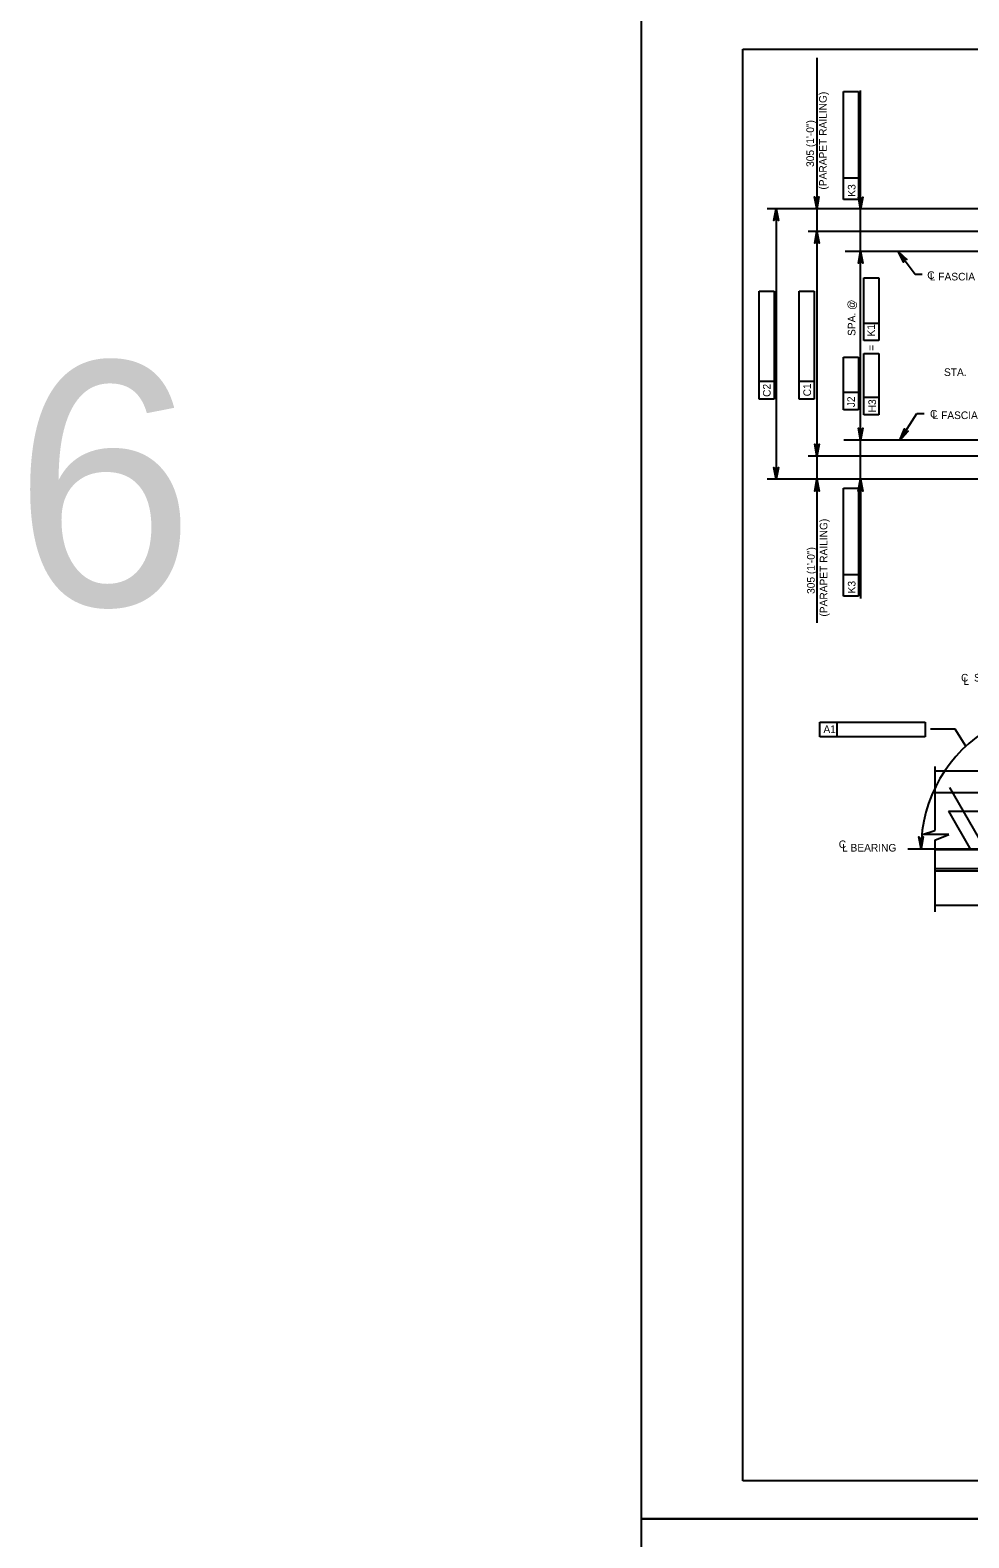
# Model space of a CAD drawing. Extents: x 638175 to 640495, y 294277 to 298435.
# Drawn here: x 638195 to 638564, y 294864 to 295458 of the extents above; entities that cross this region are included whole.
import ezdxf

# ---------------------------------------------------------------- set-up
doc = ezdxf.new("R2010")
doc.units = 0
for name, color, linetype in [('2', 7, 'Continuous'), ('3', 7, 'Continuous'), ('4', 7, 'Continuous'), ('5', 7, 'Continuous'), ('53', 7, 'Continuous'), ('8', 7, 'Continuous'), ('PLT-BNDY', 7, 'Continuous')]:
    doc.layers.add(name, color=color, linetype=linetype)

# ---------------------------------------------------------------- blocks, each defined once
blk = doc.blocks.new('AR')
at = {"layer": '4'}
blk.add_lwpolyline([(5, 0.833375), (5, -0.833375), (0, 0)], close=True, dxfattribs=at)

msp = doc.modelspace()

# ---------------------------------------------------------------- linework, layer by layer
at = {"layer": '2'}
for p, q in [((638475.46, 294886.46), (638475.46, 295450.46)), ((638475.46, 295450.46), (639261.46, 295450.46)), ((639261.46, 294886.46), (638475.46, 294886.46))]:
    msp.add_line(p, q, dxfattribs=at)
at = {"layer": '3'}
for p, q in [((638551.02, 295167.79), (638551.02, 295142.64)), ((638551.02, 295166.18), (638651.75, 295166.18)), ((638556.84, 295159.53), (638584.62, 295111.3)), ((638551.02, 295157.57), (638651.75, 295157.57)), ((638556.45, 295150.19), (638565.29, 295134.83)), ((638556.45, 295150.19), (638580.44, 295150.19)), ((638546.26, 295141.01), (638551.02, 295142.64)), ((638556.53, 295141.01), (638546.26, 295141.01)), ((638551.02, 295138.77), (638556.53, 295141.01)), ((638551.02, 295138.77), (638551.02, 295110.55)), ((638551.02, 295113.27), (638601.7, 295113.27))]:
    msp.add_line(p, q, dxfattribs=at)
at = {"layer": '4'}
for p, q in [((638504.6, 295447.04), (638504.6, 295224.4)), ((638515.12, 295391.26), (638515.12, 295433.78)), ((638515.12, 295433.78), (638521.03, 295433.78)), ((638521.03, 295433.78), (638521.03, 295391.26)), ((638521.8, 295362.21), (638521.8, 295434.13)), ((638521.03, 295399.64), (638515.12, 295399.64)), ((638521.03, 295391.26), (638515.12, 295391.26)), ((638521.8, 295390.3), (638521.8, 295393.14)), ((638657.4, 295387.6), (638485.03, 295387.6)), ((638488.54, 295387.6), (638488.54, 295281.03)), ((638667.7, 295378.63), (638501.09, 295378.63)), ((638863.78, 295370.8), (638515.73, 295370.8)), ((638536.58, 295370.8), (638543.26, 295361.87)), ((638521.8, 295280.88), (638521.8, 295362.21)), ((638543.26, 295361.87), (638546.09, 295361.87)), ((638481.87, 295355.15), (638487.77, 295355.15)), ((638481.87, 295312.63), (638481.87, 295355.15)), ((638487.77, 295355.15), (638487.77, 295312.63)), ((638497.59, 295312.61), (638497.59, 295355.13)), ((638497.59, 295355.13), (638503.5, 295355.13)), ((638503.5, 295355.13), (638503.5, 295312.61)), ((638523.09, 295360.37), (638529, 295360.37)), ((638523.09, 295335.72), (638523.09, 295360.37)), ((638529, 295360.37), (638529, 295335.72)), ((638529, 295342.42), (638523.09, 295342.42)), ((638529, 295335.72), (638523.09, 295335.72)), ((638515.1, 295329.07), (638521, 295329.07)), ((638515.1, 295308.35), (638515.1, 295329.07)), ((638521, 295329.07), (638521, 295308.35)), ((638523.09, 295306.34), (638523.09, 295330.59)), ((638523.09, 295330.59), (638529, 295330.59)), ((638529, 295330.59), (638529, 295306.34)), ((638487.77, 295319.52), (638481.87, 295319.52)), ((638503.5, 295319.5), (638497.59, 295319.5)), ((638521, 295315.24), (638515.1, 295315.24)), ((638529, 295313.23), (638523.09, 295313.23)), ((638487.77, 295312.63), (638481.87, 295312.63)), ((638503.5, 295312.61), (638497.59, 295312.61)), ((638521, 295308.35), (638515.1, 295308.35)), ((638529, 295306.34), (638523.09, 295306.34)), ((638537.32, 295296.45), (638544.03, 295306.88)), ((638544.03, 295306.88), (638546.86, 295306.88)), ((638825.02, 295296.45), (638515.26, 295296.45)), ((638609.48, 295290.15), (638501.09, 295290.15)), ((638598.75, 295281.03), (638485.03, 295281.03)), ((638515.12, 295234.98), (638515.12, 295277.5)), ((638515.12, 295277.5), (638521.03, 295277.5)), ((638521.03, 295277.5), (638521.03, 295234.98)), ((638521.8, 295278.31), (638521.8, 295275.47)), ((638521.8, 295275.47), (638521.8, 295234.09)), ((638521.03, 295243.37), (638515.12, 295243.37)), ((638521.03, 295234.98), (638515.12, 295234.98)), ((638505.74, 295185.34), (638547.26, 295185.34)), ((638505.74, 295179.57), (638505.74, 295185.34)), ((638512.63, 295179.57), (638512.63, 295185.34)), ((638547.26, 295185.34), (638547.26, 295179.57)), ((638559.08, 295182.58), (638549.36, 295182.58)), ((638563.32, 295175.91), (638559.08, 295182.58)), ((638547.26, 295179.57), (638505.74, 295179.57)), ((638540.38, 295135.42), (638666.83, 295135.42))]:
    msp.add_line(p, q, dxfattribs=at)
for points in [[(638504.54, 295387.65), (638503.67, 295392.31), (638503.91, 295391.95), (638504.23, 295391.77), (638504.54, 295391.71), (638504.85, 295391.77), (638505.16, 295391.95), (638505.41, 295392.31), (638504.54, 295387.65), (638505.16, 295391.95), (638504.85, 295391.77), (638504.54, 295387.65), (638504.54, 295391.71), (638504.23, 295391.77), (638504.54, 295387.65), (638503.91, 295391.95)], [(638521.8, 295387.46), (638520.93, 295392.12), (638521.18, 295391.77), (638521.49, 295391.58), (638521.8, 295391.53), (638522.12, 295391.58), (638522.43, 295391.77), (638522.68, 295392.12), (638521.8, 295387.46), (638522.43, 295391.77), (638522.12, 295391.58), (638521.8, 295387.46), (638521.8, 295391.53), (638521.49, 295391.58), (638521.8, 295387.46), (638521.18, 295391.77)], [(638488.54, 295387.6), (638489.41, 295382.94), (638489.17, 295383.3), (638488.85, 295383.49), (638488.54, 295383.54), (638488.23, 295383.49), (638487.92, 295383.3), (638487.67, 295382.94), (638488.54, 295387.6), (638487.92, 295383.3), (638488.23, 295383.49), (638488.54, 295387.6), (638488.54, 295383.54), (638488.85, 295383.49), (638488.54, 295387.6), (638489.17, 295383.3)], [(638504.6, 295378.63), (638505.48, 295373.97), (638505.23, 295374.33), (638504.92, 295374.52), (638504.6, 295374.57), (638504.29, 295374.52), (638503.98, 295374.33), (638503.73, 295373.97), (638504.6, 295378.63), (638503.98, 295374.33), (638504.29, 295374.52), (638504.6, 295378.63), (638504.6, 295374.57), (638504.92, 295374.52), (638504.6, 295378.63), (638505.23, 295374.33)], [(638521.8, 295370.8), (638522.68, 295366.14), (638522.43, 295366.5), (638522.12, 295366.68), (638521.8, 295366.74), (638521.49, 295366.68), (638521.18, 295366.5), (638520.93, 295366.14), (638521.8, 295370.8), (638521.18, 295366.5), (638521.49, 295366.68), (638521.8, 295370.8), (638521.8, 295366.74), (638522.12, 295366.68), (638521.8, 295370.8), (638522.43, 295366.5)], [(638536.58, 295370.8), (638540.07, 295367.59), (638539.66, 295367.73), (638539.29, 295367.69), (638539.01, 295367.55), (638538.79, 295367.32), (638538.65, 295366.98), (638538.67, 295366.54), (638536.58, 295370.8), (638538.65, 295366.98), (638538.79, 295367.32), (638536.58, 295370.8), (638539.01, 295367.55), (638539.29, 295367.69), (638536.58, 295370.8), (638539.66, 295367.73)], [(638521.8, 295296.45), (638520.93, 295301.11), (638521.18, 295300.75), (638521.49, 295300.56), (638521.8, 295300.51), (638522.12, 295300.56), (638522.43, 295300.75), (638522.68, 295301.11), (638521.8, 295296.45), (638522.43, 295300.75), (638522.12, 295300.56), (638521.8, 295296.45), (638521.8, 295300.51), (638521.49, 295300.56), (638521.8, 295296.45), (638521.18, 295300.75)], [(638537.32, 295296.45), (638539.11, 295300.84), (638539.12, 295300.4), (638539.28, 295300.08), (638539.52, 295299.86), (638539.81, 295299.74), (638540.17, 295299.73), (638540.58, 295299.9), (638537.32, 295296.45), (638540.17, 295299.73), (638539.81, 295299.74), (638537.32, 295296.45), (638539.52, 295299.86), (638539.28, 295300.08), (638537.32, 295296.45), (638539.12, 295300.4)], [(638504.6, 295290.15), (638503.73, 295294.81), (638503.98, 295294.45), (638504.29, 295294.26), (638504.6, 295294.21), (638504.92, 295294.26), (638505.23, 295294.45), (638505.48, 295294.81), (638504.6, 295290.15), (638505.23, 295294.45), (638504.92, 295294.26), (638504.6, 295290.15), (638504.6, 295294.21), (638504.29, 295294.26), (638504.6, 295290.15), (638503.98, 295294.45)], [(638488.54, 295281.03), (638487.67, 295285.69), (638487.92, 295285.33), (638488.23, 295285.15), (638488.54, 295285.09), (638488.85, 295285.15), (638489.17, 295285.33), (638489.41, 295285.69), (638488.54, 295281.03), (638489.17, 295285.33), (638488.85, 295285.15), (638488.54, 295281.03), (638488.54, 295285.09), (638488.23, 295285.15), (638488.54, 295281.03), (638487.92, 295285.33)], [(638504.6, 295281.03), (638505.48, 295276.37), (638505.23, 295276.73), (638504.92, 295276.91), (638504.6, 295276.97), (638504.29, 295276.91), (638503.98, 295276.73), (638503.73, 295276.37), (638504.6, 295281.03), (638503.98, 295276.73), (638504.29, 295276.91), (638504.6, 295281.03), (638504.6, 295276.97), (638504.92, 295276.91), (638504.6, 295281.03), (638505.23, 295276.73)], [(638521.79, 295281.03), (638522.66, 295276.37), (638522.41, 295276.73), (638522.1, 295276.91), (638521.79, 295276.97), (638521.47, 295276.91), (638521.16, 295276.73), (638520.91, 295276.37), (638521.79, 295281.03), (638521.16, 295276.73), (638521.47, 295276.91), (638521.79, 295281.03), (638521.79, 295276.97), (638522.1, 295276.91), (638521.79, 295281.03), (638522.41, 295276.73)], [(638545.64, 295135.42), (638544.76, 295140.08), (638545.01, 295139.72), (638545.32, 295139.53), (638545.64, 295139.48), (638545.95, 295139.53), (638546.26, 295139.72), (638546.51, 295140.08), (638545.64, 295135.42), (638546.26, 295139.72), (638545.95, 295139.53), (638545.64, 295135.42), (638545.64, 295139.48), (638545.32, 295139.53), (638545.64, 295135.42), (638545.01, 295139.72)]]:
    msp.add_lwpolyline(points, dxfattribs=at)
for points in [[(638521.33, 295390.3), (638522.28, 295390.3), (638521.8, 295387.46)], [(638521.33, 295367.97), (638522.28, 295367.97), (638521.8, 295370.8)], [(638537.9, 295368.25), (638538.66, 295368.81), (638536.58, 295370.8)], [(638521.33, 295299.28), (638522.28, 295299.28), (638521.8, 295296.45)], [(638539.25, 295298.58), (638538.46, 295299.09), (638537.32, 295296.45)], [(638521.33, 295278.31), (638522.28, 295278.31), (638521.8, 295281.15)]]:
    msp.add_lwpolyline(points, close=True, dxfattribs=at)
at = {"layer": '5'}
msp.add_arc((638600.84, 295135.42), 55.2, 119.77013, 180, dxfattribs=at)
at = {"layer": '8'}
for p, q in [((638581.26, 295135.06), (638551.02, 295135.06)), ((638581.26, 295127.58), (638551.02, 295127.58)), ((638581.26, 295126.59), (638551.02, 295126.59))]:
    msp.add_line(p, q, dxfattribs=at)
at = {"layer": 'PLT-BNDY'}
for points in [[(638435.46, 295465.46), (639276.46, 295465.46), (639276.46, 294871.46), (638435.46, 294871.46)], [(638435.46, 294871.46), (639276.46, 294871.46), (639276.46, 294277.46), (638435.46, 294277.46)]]:
    msp.add_lwpolyline(points, close=True, dxfattribs=at)

# ---------------------------------------------------------------- block references
at = {"layer": '4', "xscale": 0.5905511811, "yscale": 0.5905511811}
for p, rotation in [((638504.6, 295387.6), 90), ((638488.54, 295387.6), -90.00000000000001), ((638504.6, 295378.63), -90.00000000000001), ((638504.6, 295290.15), 90), ((638488.54, 295281.03), 90), ((638504.6, 295281.03), -90.00000000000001)]:
    msp.add_blockref('AR', p, dxfattribs=dict(at, rotation=rotation))

# ---------------------------------------------------------------- texts
at = {"layer": '4'}
for s, p in [('(PARAPET RAILING)', (638508.44, 295395.14)), ('305 (1\'-0")', (638503.44, 295404.07)), ('K3', (638519.79, 295392.35)), ('SPA. @', (638519.77, 295337.48)), ('K1', (638527.45, 295337.27)), ('=', (638527.5, 295331.6)), ('C2', (638486.34, 295313.47)), ('C1', (638502.25, 295313.68)), ('J2', (638519.58, 295309.41)), ('H3', (638527.88, 295307.38)), ('(PARAPET RAILING)', (638508.72, 295226.91)), ('305 (1\'-0")', (638503.72, 295235.84)), ('K3', (638519.79, 295236.07))]:
    msp.add_text(s, height=3, rotation=90, dxfattribs=at).set_placement(p)
for s, p in [('C', (638548.07, 295359.93)), ('L FASCIA BEAM', (638549.09, 295359.35)), ('STA.', (638554.68, 295321.71)), ('C', (638549.16, 295305.31)), ('L FASCIA BEAM', (638550.18, 295304.73)), ('C  STEEL BEAM', (638561.38, 295201.34)), ('L', (638562.32, 295200)), ('A1', (638507.17, 295181.05)), ('C', (638513.21, 295135.71)), ('L BEARING', (638514.5, 295134.34))]:
    msp.add_text(s, height=3, dxfattribs=at).set_placement(p)
at = {"layer": '53'}
msp.add_text('6', height=96, dxfattribs=at).set_placement((638188.01, 295231.29))

doc.saveas('drawing.dxf')
